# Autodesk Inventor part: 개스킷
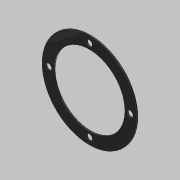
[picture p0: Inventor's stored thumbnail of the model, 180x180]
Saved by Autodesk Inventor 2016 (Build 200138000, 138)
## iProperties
Created: 2019-05
Part Number: 개스킷
Material: 고무
Document SubType Name: Modeling
Designer: mduedu
Density: 1 g/cm^3
Appearance: 고무 - 검은색 - 버전 1.1
Author: mduedu
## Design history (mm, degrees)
sketch "스케치1"
  geometry: C1 r 27 at (0, 0); C2 r 36 at (0, 0); 1 further point
  constraints: 2 centre point, 2 coincident
  dimensions: "d0" = 54 diameter of C1; "d1" = 72 diameter of C2
extrude "돌출1" new body sketch "스케치1" distance "d2" = 1; taper "d3" = 0 deg
sketch "스케치2" dims "d4" = 62
  geometry: C1 r 2.25 at (0, 31); 2 further points
  constraints: 2 vertical alignment, 1 centre point, 1 coincident, 2 other
  dimensions: "d5" = 4.5 diameter of C1
extrude "돌출2" cut sketch "스케치2" stored distance "d6" = 10; taper "d7" = 0 deg
node "솔리드1"
pattern_circular "원형 패턴1" dims angle "d9" = 360 deg
